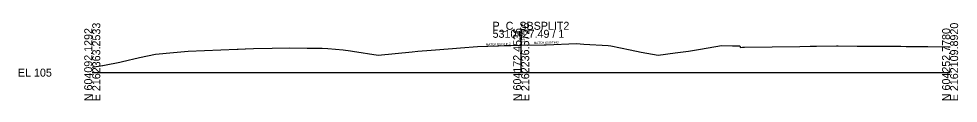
# Model space of a CAD drawing. Extents: x -26 to 1303, y -10 to 12033.
# Drawn here: x 974.3 to 1302.8, y 3490.3 to 3517.8 of the extents above; entities that cross this region are included whole.
import ezdxf

# ---------------------------------------------------------------- set-up
doc = ezdxf.new("R2010")
doc.units = 0
for name, color, linetype in [('RD_GPK_XS_Cell', 7, 'Continuous'), ('RD_XS_ExGround', 7, 'Continuous'), ('RD_XS_TX_Elev_EX', 7, 'Continuous'), ('RD_XS_TX_Elev_PR', 7, 'Continuous'), ('RD_XS_TX_Slope', 7, 'Continuous')]:
    doc.layers.add(name, color=color, linetype=linetype)

msp = doc.modelspace()

# ---------------------------------------------------------------- linework, layer by layer
at = {"layer": 'RD_GPK_XS_Cell'}
for p, q in [((1150, 3500), (1150, 3515)), ((1000, 3500), (1150, 3500)), ((1150, 3500), (1300, 3500))]:
    msp.add_line(p, q, dxfattribs=at)
at = {"layer": 'RD_XS_ExGround'}
msp.add_lwpolyline([(1000, 3501.96), (1003.58, 3502.49), (1003.75, 3502.53), (1004.28, 3502.64), (1009.6, 3503.71), (1013.06, 3504.48), (1014.08, 3504.76), (1016.52, 3505.28), (1022.09, 3506.5), (1028.41, 3507.06), (1033.53, 3507.51), (1050.68, 3508.23), (1051.01, 3508.24), (1053.45, 3508.28), (1053.61, 3508.33), (1056.37, 3508.41), (1062.97, 3508.55), (1068.91, 3508.69), (1075.1, 3508.59), (1080.36, 3508.52), (1082.43, 3508.5), (1087.76, 3507.94), (1090.27, 3507.66), (1090.97, 3507.57), (1100.02, 3506.09), (1111.92, 3507.29), (1113.89, 3507.5), (1118.5, 3507.87), (1126.04, 3508.49), (1128.78, 3508.72), (1134.76, 3509.19), (1142.06, 3509.44), (1144.05, 3509.5), (1145.91, 3509.5), (1146.44, 3509.5), (1149.95, 3509.67), (1158, 3509.77), (1158.21, 3509.77), (1158.34, 3509.77), (1158.78, 3509.79), (1169.4, 3510.16), (1171.94, 3510.01), (1180.42, 3509.5), (1181.35, 3509.34), (1188.08, 3507.99), (1191.92, 3507.15), (1197.95, 3506.09), (1203.89, 3506.91), (1208.52, 3507.51), (1212.76, 3508.26), (1220.02, 3509.5), (1223.93, 3509.41), (1226.49, 3509.35), (1226.56, 3509.14), (1226.64, 3508.85), (1227.45, 3508.88), (1228.05, 3508.9), (1247.4, 3509.16), (1251.06, 3509.21), (1251.34, 3509.21), (1253.33, 3509.23), (1260.33, 3509.33), (1260.81, 3509.33), (1267.51, 3509.28), (1270.18, 3509.28), (1277.84, 3509.22), (1282.74, 3509.21), (1284.67, 3509.19), (1288.67, 3509.18), (1289.72, 3509.18), (1292.26, 3509.16), (1299.27, 3509.03), (1300, 3509.01)], dxfattribs=at)

# ---------------------------------------------------------------- texts
at = {"layer": 'RD_GPK_XS_Cell'}
for s, p in [('N 604092.1292', (1000, 3490)), ('E 2162363.2533', (1002.8, 3490)), ('N 604172.4536', (1150, 3490)), ('E 2162236.5726', (1152.8, 3490)), ('N 604252.7780', (1300, 3490)), ('E 2162109.8920', (1302.8, 3490))]:
    msp.add_text(s, height=2.8, rotation=90, dxfattribs=at).set_placement(p)
for s, p in [('P_C_SBSPLIT2', (1140, 3515)), ('5310+27.49 / 1', (1140, 3512.2)), ('EL 105', (974, 3498.6))]:
    msp.add_text(s, height=2.8, dxfattribs=at).set_placement(p)
at = {"layer": 'RD_XS_TX_Elev_EX'}
msp.add_text('114.68', height=0.6, rotation=90, dxfattribs=at).set_placement((1149.68, 3510.62))
at = {"layer": 'RD_XS_TX_Elev_PR'}
msp.add_text('114.68', height=1, rotation=90, dxfattribs=at).set_placement((1151.27, 3510.37))
at = {"layer": 'RD_XS_TX_Slope'}
for p in [(1137.65, 3509.47), (1154.4, 3510.03)]:
    msp.add_text('MATCH EXISTING', height=0.75, rotation=1.6039, dxfattribs=at).set_placement(p)

doc.saveas('drawing.dxf')
